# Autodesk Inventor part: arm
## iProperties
Author: vincent molino
Shininess: 100.0
Angle Display Precision: 2
Document Length Units: 11272
Document Angle Units: 11286
Document Time Units: 11279
Document Mass Units: 11290
Document Length Units Precision: 3
Document Angle Units Precision: 2
Compacted: True
PropertySet Name: _Private Model Information
Created: 2002-01
Part Number: arm
Document SubType Name: Modeling
Designer: vincent molino
Control State: 0
Master: False
Checked Out: False
PropertySet Name: Design Tracking Control
Density: 0.0
Volumn: 0.0
Area: 0.0
PropertySet Name: Model Information
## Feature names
1. Extrusion1
2. Mirror1
3. Extrusion3
4. Extrusion4
5. Mirror2
6. Extrusion5
7. Extrusion6
8. Fillet1
